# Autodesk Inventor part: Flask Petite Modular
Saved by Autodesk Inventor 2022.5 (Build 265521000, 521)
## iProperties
Created: 2025-01
Part Number: Flask Petite Modular
Material: Generic
Document SubType Name: Modeling
Designer: AdminForWorker
Density: 1 g/cm^3
Appearance: Default
Title: Flask Petite Modular
Author: AdminForWorker
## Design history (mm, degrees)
feature "Flask Petite Modular"
body "Solid1"
